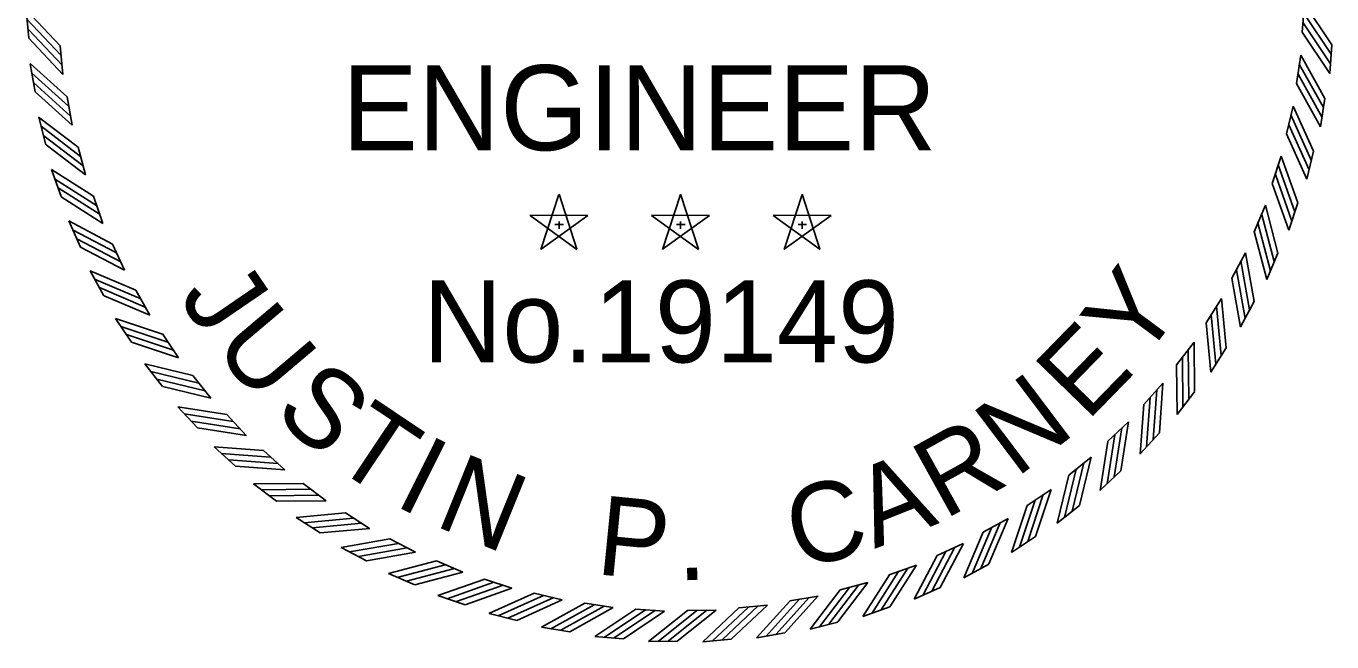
# Model space of a CAD drawing. Extents: x 16 to 1228740, y 11 to 152440.
# Drawn here: x 18.963 to 19.1347, y 11 to 11.081 of the extents above; entities that cross this region are included whole.
import ezdxf

# ---------------------------------------------------------------- set-up
doc = ezdxf.new("R2010")
doc.units = 0
doc.layers.add('STAMP_JUSTIN', color=7, linetype='Continuous')

msp = doc.modelspace()

# ---------------------------------------------------------------- linework, layer by layer
at = {"layer": 'STAMP_JUSTIN'}
for p, q in [((18.96332, 11.0794), (18.96297, 11.08315)), ((19.13107, 11.08395), (19.13079, 11.08018)), ((18.96778, 11.07464), (18.96744, 11.0784)), ((19.13469, 11.07852), (19.13441, 11.07476)), ((18.96416, 11.07234), (18.96351, 11.07605)), ((19.13061, 11.07718), (19.13003, 11.07345)), ((18.96901, 11.06797), (18.96835, 11.07169)), ((19.13378, 11.07147), (19.13319, 11.06775)), ((19.1296, 11.07047), (19.12871, 11.0668)), ((18.96558, 11.06538), (18.96463, 11.06902)), ((18.97077, 11.06142), (18.96981, 11.06508)), ((19.13228, 11.06453), (19.13139, 11.06086)), ((19.12804, 11.06387), (19.12685, 11.06029)), ((18.96758, 11.05856), (18.96632, 11.06211)), ((19.03539, 11.05163), (19.03305, 11.05887)), ((19.05138, 11.05163), (19.04904, 11.05887)), ((19.06737, 11.05163), (19.06503, 11.05887)), ((18.97307, 11.05504), (18.97181, 11.05861)), ((19.03304, 11.05886), (19.03068, 11.05162)), ((19.04903, 11.05886), (19.04668, 11.05162)), ((19.06502, 11.05886), (19.06267, 11.05162)), ((19.12594, 11.05743), (19.12445, 11.05395)), ((19.13022, 11.05773), (19.12903, 11.05415)), ((19.03684, 11.0561), (19.02923, 11.05611)), ((19.02924, 11.0561), (19.03539, 11.05162)), ((19.03069, 11.05163), (19.03685, 11.0561)), ((19.05284, 11.0561), (19.04523, 11.05611)), ((19.04523, 11.0561), (19.05138, 11.05162)), ((19.04668, 11.05163), (19.05285, 11.0561)), ((19.06883, 11.0561), (19.06122, 11.05611)), ((19.06122, 11.0561), (19.06738, 11.05162)), ((19.06267, 11.05163), (19.06884, 11.0561)), ((18.97013, 11.05192), (18.96858, 11.05536)), ((19.0325, 11.05488), (19.03363, 11.05488)), ((19.03305, 11.05529), (19.03305, 11.05433)), ((19.04849, 11.05488), (19.04962, 11.05488)), ((19.04904, 11.05529), (19.04904, 11.05433)), ((19.06448, 11.05488), (19.06561, 11.05488)), ((19.06503, 11.05529), (19.06503, 11.05433)), ((18.97589, 11.04888), (18.97435, 11.05232)), ((19.12331, 11.05117), (19.12154, 11.04783)), ((19.1276, 11.05112), (19.12612, 11.04765)), ((18.97321, 11.04552), (18.97139, 11.04882)), ((18.97922, 11.04296), (18.97739, 11.04627)), ((19.12018, 11.04516), (19.11814, 11.04198)), ((19.12445, 11.04475), (19.12269, 11.04142)), ((18.97682, 11.0394), (18.97473, 11.04254)), ((18.98301, 11.03734), (18.98092, 11.04049)), ((19.11656, 11.03943), (19.11426, 11.03642)), ((19.12078, 11.03866), (19.11875, 11.03549)), ((18.98092, 11.03359), (18.97858, 11.03655)), ((18.98726, 11.03206), (18.98491, 11.03502)), ((19.11247, 11.03401), (19.10994, 11.03121)), ((19.11662, 11.0329), (19.11433, 11.02991)), ((18.98549, 11.02815), (18.98291, 11.0309)), ((18.99193, 11.02714), (18.98935, 11.0299)), ((19.10796, 11.02895), (19.1052, 11.02636)), ((19.112, 11.0275), (19.10947, 11.02471)), ((18.99049, 11.0231), (18.98769, 11.02563)), ((18.99699, 11.02263), (18.99419, 11.02516)), ((19.10304, 11.02428), (19.10008, 11.02193)), ((19.10695, 11.0225), (19.1042, 11.01993)), ((18.99588, 11.01848), (18.99289, 11.02077)), ((19.00241, 11.01854), (18.9994, 11.02084)), ((19.09776, 11.02003), (19.09461, 11.01793)), ((19.1015, 11.01794), (19.09855, 11.0156)), ((19.00165, 11.01432), (18.99847, 11.01635)), ((19.00814, 11.01492), (19.00496, 11.01696)), ((19.09214, 11.01623), (19.08883, 11.0144)), ((19.01416, 11.01179), (19.01082, 11.01356)), ((19.08622, 11.01291), (19.08278, 11.01136)), ((19.0957, 11.01384), (19.09256, 11.01175)), ((19.00773, 11.01065), (19.0044, 11.01241)), ((19.02041, 11.00916), (19.01693, 11.01065)), ((19.08006, 11.01009), (19.07649, 11.00883)), ((19.08958, 11.01023), (19.08628, 11.00841)), ((19.0141, 11.0075), (19.01064, 11.00898)), ((19.02686, 11.00706), (19.02327, 11.00825)), ((19.07368, 11.00779), (19.07002, 11.00683)), ((19.02071, 11.00488), (19.01713, 11.00607)), ((19.03346, 11.0055), (19.02978, 11.00639)), ((19.06713, 11.00602), (19.06341, 11.00537)), ((19.08318, 11.00714), (19.07974, 11.0056)), ((19.04016, 11.00449), (19.03643, 11.00507)), ((19.04693, 11.00403), (19.04316, 11.00431)), ((19.05371, 11.00414), (19.04993, 11.0041)), ((19.06046, 11.0048), (19.0567, 11.00446)), ((19.07654, 11.00459), (19.07299, 11.00334)), ((19.02751, 11.00282), (19.02385, 11.00371)), ((19.06972, 11.0026), (19.06608, 11.00164)), ((19.03446, 11.00132), (19.03073, 11.00191)), ((19.0415, 11.00041), (19.03774, 11.00069)), ((19.06276, 11.00118), (19.05905, 11.00052)), ((19.0486, 11.00008), (19.04483, 11.00004)), ((19.0557, 11.00034), (19.05195, 10.99999))]:
    msp.add_line(p, q, dxfattribs=at)
for points in [[(18.96744, 11.0784), (18.96297, 11.08315)], [(19.13106, 11.08395), (19.13469, 11.07853)], [(18.96754, 11.07715), (18.96307, 11.0819)], [(19.1309, 11.08143), (19.13452, 11.07601)], [(19.13096, 11.08274), (19.13459, 11.07732)], [(18.96769, 11.07585), (18.96322, 11.0806)], [(19.13079, 11.08018), (19.13442, 11.07476)], [(18.96779, 11.07464), (18.96332, 11.07939)], [(18.96835, 11.07169), (18.9635, 11.07606)], [(19.13061, 11.07718), (19.13377, 11.07148)], [(18.96855, 11.07045), (18.96371, 11.07482)], [(19.13024, 11.07469), (19.1334, 11.06898)], [(19.13041, 11.07599), (19.13357, 11.07028)], [(18.96881, 11.06916), (18.96397, 11.07353)], [(19.13003, 11.07345), (19.13319, 11.06775)], [(18.96901, 11.06797), (18.96417, 11.07233)], [(19.1293, 11.0693), (19.13198, 11.06336)], [(19.1296, 11.07048), (19.13228, 11.06453)], [(18.96981, 11.06507), (18.96462, 11.06903)], [(18.97012, 11.06385), (18.96493, 11.06781)], [(19.12902, 11.06802), (19.1317, 11.06208)], [(18.97048, 11.0626), (18.96529, 11.06655)], [(19.12871, 11.06681), (19.13139, 11.06086)], [(18.97078, 11.06142), (18.96559, 11.06537)], [(19.12764, 11.06273), (19.12982, 11.05658)], [(19.12804, 11.06388), (19.13022, 11.05773)], [(18.97181, 11.0586), (18.96632, 11.06211)], [(18.97222, 11.05741), (18.96672, 11.06092)], [(19.12726, 11.06148), (19.12944, 11.05533)], [(18.97269, 11.05619), (18.96719, 11.0597)], [(19.12685, 11.06029), (19.12903, 11.05415)], [(18.97308, 11.05504), (18.96758, 11.05855)], [(19.12594, 11.05743), (19.1276, 11.05113)], [(19.12545, 11.05632), (19.12711, 11.05001)], [(18.97434, 11.05232), (18.96858, 11.05536)], [(18.97485, 11.05117), (18.96908, 11.05421)], [(19.12446, 11.05396), (19.12612, 11.04765)], [(19.12496, 11.05511), (19.12663, 11.0488)], [(18.97541, 11.04998), (18.96964, 11.05303)], [(18.9759, 11.04887), (18.97013, 11.05192)], [(19.12331, 11.05118), (19.12445, 11.04476)], [(18.97739, 11.04626), (18.97139, 11.04882)], [(19.12214, 11.04894), (19.12328, 11.04252)], [(19.12273, 11.05011), (19.12387, 11.04369)], [(18.97798, 11.04516), (18.97198, 11.04772)], [(19.12155, 11.04784), (19.12269, 11.04141)], [(18.97864, 11.04403), (18.97264, 11.04659)], [(18.97922, 11.04296), (18.97322, 11.04552)], [(19.12018, 11.04517), (19.12078, 11.03867)], [(19.11951, 11.04415), (19.12012, 11.03766)], [(18.98092, 11.04048), (18.97473, 11.04254)], [(19.11814, 11.04198), (19.11875, 11.03549)], [(19.11883, 11.04303), (19.11943, 11.03654)], [(18.9816, 11.03943), (18.97541, 11.04149)], [(18.98235, 11.03836), (18.97616, 11.04041)], [(18.98302, 11.03734), (18.97683, 11.0394)], [(19.11581, 11.03847), (19.11588, 11.03195)], [(19.11656, 11.03943), (19.11662, 11.03291)], [(18.98491, 11.03501), (18.97857, 11.03655)], [(19.11504, 11.03742), (19.11511, 11.03089)], [(18.98568, 11.03402), (18.97935, 11.03556)], [(19.11427, 11.03642), (19.11433, 11.0299)], [(18.98652, 11.03301), (18.98018, 11.03455)], [(18.98727, 11.03206), (18.98093, 11.03359)], [(19.11165, 11.03312), (19.11118, 11.02662)], [(19.11247, 11.03402), (19.112, 11.02751)], [(19.1108, 11.03213), (19.11032, 11.02563)], [(18.98935, 11.02989), (18.9829, 11.0309)], [(18.9902, 11.02897), (18.98375, 11.02998)], [(19.10995, 11.03121), (19.10947, 11.0247)], [(18.99112, 11.02803), (18.98467, 11.02904)], [(18.99194, 11.02714), (18.98549, 11.02815)], [(19.10707, 11.02813), (19.10606, 11.02169)], [(19.10796, 11.02895), (19.10695, 11.02251)], [(19.10521, 11.02637), (19.1042, 11.01992)], [(19.10613, 11.02722), (19.10512, 11.02077)], [(18.99419, 11.02515), (18.98768, 11.02563)], [(18.99511, 11.0243), (18.98861, 11.02478)], [(18.9961, 11.02345), (18.9896, 11.02392)], [(18.997, 11.02262), (18.99049, 11.0231)], [(19.10209, 11.02354), (19.10055, 11.0172)], [(19.10304, 11.02428), (19.10151, 11.01794)], [(19.10009, 11.02193), (19.09855, 11.01559)], [(19.10108, 11.0227), (19.09954, 11.01636)], [(18.99941, 11.02083), (18.99288, 11.02077)], [(19.0004, 11.02006), (18.99388, 11.01999)], [(19.09776, 11.02004), (19.0957, 11.01384)], [(19.00146, 11.01929), (18.99493, 11.01922)], [(19.00241, 11.01854), (18.99589, 11.01848)], [(19.09462, 11.01793), (19.09256, 11.01174)], [(19.09567, 11.01862), (19.09361, 11.01243)], [(19.09674, 11.01937), (19.09469, 11.01318)], [(19.00496, 11.01696), (18.99847, 11.01635)], [(19.00601, 11.01627), (18.99952, 11.01566)], [(19.09214, 11.01624), (19.08958, 11.01024)], [(19.00713, 11.01559), (19.00064, 11.01498)], [(19.00815, 11.01492), (19.00165, 11.01432)], [(19.08884, 11.0144), (19.08628, 11.0084)], [(19.08994, 11.015), (19.08738, 11.009)], [(19.09107, 11.01566), (19.08851, 11.00966)], [(19.01082, 11.01355), (19.0044, 11.01241)], [(19.01192, 11.01295), (19.0055, 11.01182)], [(19.08623, 11.01292), (19.08318, 11.00715)], [(19.0131, 11.01237), (19.00667, 11.01123)], [(19.01416, 11.01179), (19.00774, 11.01065)], [(19.08278, 11.01136), (19.07974, 11.00559)], [(19.08393, 11.01187), (19.08089, 11.0061)], [(19.08512, 11.01243), (19.08207, 11.00666)], [(19.01694, 11.01064), (19.01063, 11.00898)], [(19.01809, 11.01014), (19.01178, 11.00847)], [(19.0193, 11.00965), (19.013, 11.00799)], [(19.02041, 11.00916), (19.01411, 11.0075)], [(19.07769, 11.00924), (19.07417, 11.00374)], [(19.07891, 11.0097), (19.0754, 11.00421)], [(19.08006, 11.0101), (19.07655, 11.0046)], [(19.02328, 11.00825), (19.01713, 11.00607)], [(19.02446, 11.00784), (19.01832, 11.00566)], [(19.02571, 11.00746), (19.01957, 11.00528)], [(19.0725, 11.0075), (19.06855, 11.00231)], [(19.07368, 11.00779), (19.06973, 11.00261)], [(19.0765, 11.00883), (19.07299, 11.00333)], [(19.02686, 11.00706), (19.02071, 11.00488)], [(19.02979, 11.00639), (19.02384, 11.00371)], [(19.03101, 11.00608), (19.02506, 11.0034)], [(19.03229, 11.0058), (19.02634, 11.00312)], [(19.06594, 11.00583), (19.06157, 11.00098)], [(19.06713, 11.00603), (19.06276, 11.00118)], [(19.07003, 11.00683), (19.06607, 11.00164)], [(19.07125, 11.00714), (19.06729, 11.00195)], [(19.03346, 11.0055), (19.02751, 11.00282)], [(19.03643, 11.00507), (19.03073, 11.00191)], [(19.03767, 11.00486), (19.03197, 11.0017)], [(19.03897, 11.00469), (19.03327, 11.00153)], [(19.04017, 11.00449), (19.03446, 11.00133)], [(19.04316, 11.00431), (19.03774, 11.00068)], [(19.04442, 11.0042), (19.03899, 11.00058)], [(19.04572, 11.00414), (19.0403, 11.00051)], [(19.04693, 11.00403), (19.04151, 11.00041)], [(19.04994, 11.0041), (19.04483, 11.00004)], [(19.05119, 11.0041), (19.04608, 11.00004)], [(19.0525, 11.00414), (19.04739, 11.00008)], [(19.05371, 11.00414), (19.04861, 11.00008)], [(19.0567, 11.00445), (19.05195, 10.99999)], [(19.05795, 11.00456), (19.0532, 11.00009)], [(19.05925, 11.00471), (19.0545, 11.00024)], [(19.06046, 11.00481), (19.05571, 11.00034)], [(19.06341, 11.00536), (19.05904, 11.00052)], [(19.06465, 11.00557), (19.06028, 11.00073)]]:
    msp.add_lwpolyline(points, dxfattribs=at)

# ---------------------------------------------------------------- texts
for s, height, p in [('ENGINEER', 0.011194, (19.00451, 11.06466)), ('No.19149', 0.010794, (19.01517, 11.03675))]:
    msp.add_text(s, height=height, dxfattribs=at).set_placement(p)
for s, rotation, p in [('J', 304.3679, (18.98286, 11.04535)), ('Y', 53.4433, (19.10962, 11.03646)), ('U', 310.2047, (18.98735, 11.03879)), ('E', 45.7825, (19.10247, 11.02887)), ('S', 318.9599, (18.99526, 11.02989)), ('N', 37.0272, (19.09315, 11.02146)), ('T', 326.256, (19.00283, 11.02347)), ('R', 29.0016, (19.08371, 11.01599)), ('I', 333.552, (19.01116, 11.01806)), ('N', 337.9296, (19.01646, 11.01534)), ('A', 21.7056, (19.07453, 11.0122)), ('C', 14.0448, (19.06446, 11.00951)), ('P', 354.3456, (19.03778, 11.00891)), ('.', 2.3712, (19.04867, 11.00805))]:
    msp.add_text(s, height=0.01042, rotation=rotation, dxfattribs=at).set_placement(p)

doc.saveas('drawing.dxf')
